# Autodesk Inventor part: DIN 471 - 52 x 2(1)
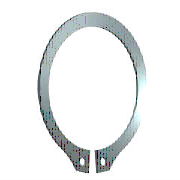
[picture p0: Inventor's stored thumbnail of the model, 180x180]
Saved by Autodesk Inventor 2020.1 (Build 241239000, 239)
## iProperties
Created: 2019-01
Part Number: DIN 471 - 52 x 2(1)
Material: Stahl, weich
Description: Sicherungsring
Document SubType Name: Modeling
Standard: DIN 471
Designer: lutzd
Standard Revision: 2011-04
Standards Organization: DIN
Language: de-DE
Size Designation: 52 x 2
Categories: <MemberInstance><Categories><Category DisplayName="Wellenteile" InternalName="7f7aeb1f-a693-4053-b835-cee3144e0d98" Mnemonic="SHFT"><Category DisplayName="Siche
Mass: 14.6386 g
Surface Area: 26.092 cm^2
Volume: 1.8648 cm^3
Density: 7.85 g/cm^3
Appearance: Semi-Polished(8)
IsCustomPart: 0
Author: lutzd
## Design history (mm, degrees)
sketch "Skizze1"
  geometry: L1 (-6, 0)-(6, 0) reference; L2 (0, 20.189)-(0, -80.536) reference; L3 (-48.09, 0)-(48.09, 0) reference; L4 (-0.625, -50.492)-(-0.625, -57.492); L5 (-0.625, -6.54)-(-0.625, -13.29); L6 (-2.795, 5.2)-(3.672, 5.2); L7 (0.625, -6.54)-(0.625, -13.29); L8 (0.625, -50.492)-(0.625, -57.492); C1 r 1.25 at (-2.5, -54.89); C2 r 1.25 at (2.5, -54.89); A1 r 24.5 centre (0, -26) between (0.625, -50.492) and (-0.625, -50.492); A2 r 29.9 centre (0, -24.7) between (6.743, -53.83) and (-6.743, -53.83); A3 r 31.498 centre (0, -26) between (-2.716, -57.381) and (-0.625, -57.492); A4 r 2.5 centre (-2.5, -54.89) between (-4.904, -55.578) and (-2.716, -57.381); A5 r 2.5 centre (-7.307, -56.265) between (-4.904, -55.578) and (-6.743, -53.83); A6 r 2.5 centre (7.307, -56.265) between (6.743, -53.83) and (4.904, -55.578); A7 r 2.5 centre (2.5, -54.89) between (2.716, -57.381) and (4.904, -55.578); A8 r 31.498 centre (0, -26) between (0.625, -57.492) and (2.716, -57.381)
  constraints: 16 point on circle, 12 end point, 10 centre point, 9 symmetric about line, 5 point on line, 4 tangent, 3 coincident, 2 horizontal, 1 perpendicular, 1 vertical, 5 other
  dimensions: "d0" = 49 diameter of A1 (= ND); "d1" = 7 distance of L4.end L4.start (= SRB2); "d6" = 0.625 distance between parallel lines of L2 L5 (= 0.25 x SD5); "d7" = 5.2 distance between parallel lines of L6 L3 (= SRB1); "d8" = 1.3 distance of A1.centre A2.centre (= 0.25 x SRB1); "d9" = 2.5 radius of A4 (= SD5); "d10" = 2.5 radius of A5 (= SD5); "d11" = 1.875 distance from line of L4 A4.centre (= 0.75 x SD5); "d12" = 2.5 diameter of C1 (= SD5); "d13" = 2.5 diameter of C2 (= SD5); "d14" = 26 distance from line of A1.centre L1 (= 0.5 x WD)
extrude "Körper" new body sketch "Skizze1" distance "d2" = 2 (= SD); taper "d3" = 0 deg
workaxis "Work Axis1"
workplane "Work Plane1"
body "Solid1"
other parameters: "WD" = 52 (= WDMIN) [user parameter; used in 1 equation term], "SD" = 2 [user parameter; used in 1 equation term], "SRB1" = 5.2 [user parameter; used in 2 equation terms], "ND" = 49 [user parameter; used in 1 equation term], "SRB2" = 7 [user parameter; used in 1 equation term], "SD5" = 2.5 [user parameter; used in 6 equation terms], "d15" = 0, "d16" = 0, "d17" = 0, "d41" = 0, "d42" = 0, "WDMIN" = 52 [user parameter; used in 1 equation term], "SD3" = 47.8 [user parameter], "WDMAX" = 55 [user parameter]
